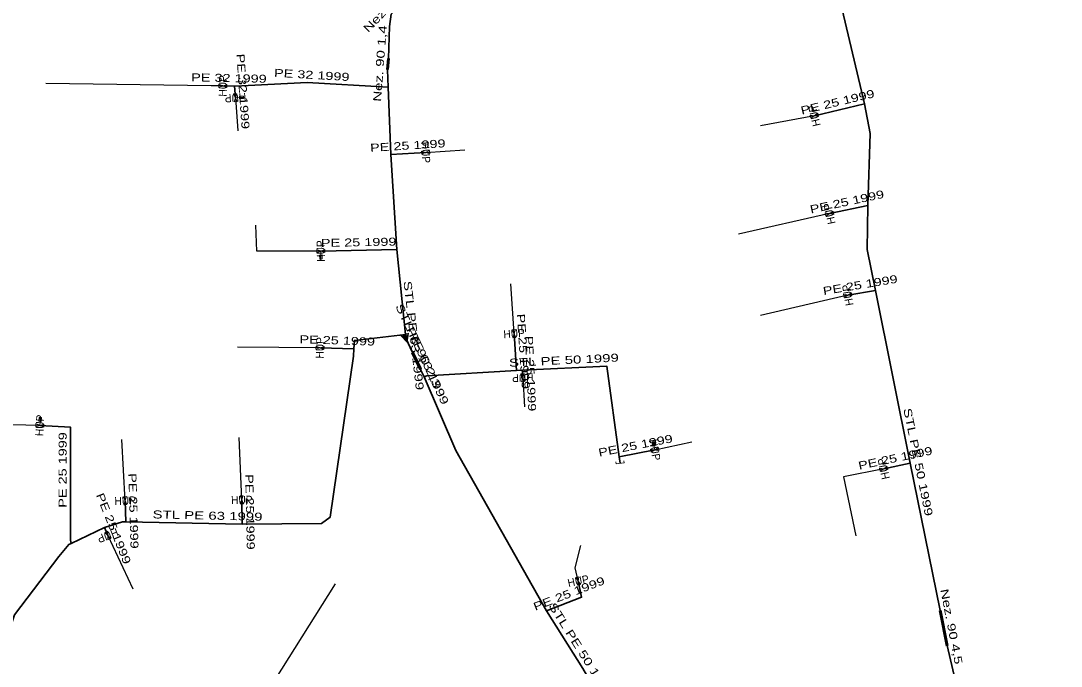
# Model space of a CAD drawing. Extents: x -737484 to -734496, y -1033882 to -1030666.
# Drawn here: x -736219.6 to -736089.6, y -1032200 to -1032119.4 of the extents above; entities that cross this region are included whole.
import ezdxf
from ezdxf.enums import TextEntityAlignment as Align

# ---------------------------------------------------------------- set-up
doc = ezdxf.new("R2010")
doc.units = 0
doc.header["$LTSCALE"] = 0.4
for name, color, linetype, lineweight in [('1', 7, 'Continuous', 13), ('18', 7, 'Continuous', 60), ('22', 7, 'Continuous', 25), ('5', 7, 'Continuous', 35), ('7', 7, 'Continuous', 35)]:
    doc.layers.add(name, color=color, linetype=linetype, lineweight=lineweight)
doc.layers.add('2', color=7, linetype='Continuous')

msp = doc.modelspace()

# ---------------------------------------------------------------- linework, layer by layer
at = {"layer": '1'}
for p, q in [((-736192.759, -1032128.988), (-736192.26, -1032128.953)), ((-736192.18, -1032129.022), (-736191.831, -1032128.998)), ((-736182.163, -1032148.715), (-736182.157, -1032149.065)), ((-736182.099, -1032148.139), (-736182.09, -1032148.638)), ((-736217.199, -1032169.929), (-736217.172, -1032169.429)), ((-736217.094, -1032169.358), (-736217.075, -1032169.009)), ((-736140.406, -1032172.411), (-736140.472, -1032172.067)), ((-736140.37, -1032172.99), (-736140.465, -1032172.499))]:
    msp.add_line(p, q, dxfattribs=at)
for points in [[(-736194.821, -1032127.699), (-736194.814, -1032127.299), (-736193.821, -1032127.716), (-736193.814, -1032127.316)], [(-736192.523, -1032129.473), (-736192.922, -1032129.501), (-736192.593, -1032128.476), (-736192.992, -1032128.504)], [(-736191.761, -1032128.918), (-736191.771, -1032128.768), (-736192.27, -1032128.803), (-736192.26, -1032128.953)], [(-736191.761, -1032128.918), (-736191.75, -1032129.067), (-736192.249, -1032129.102), (-736192.26, -1032128.953)], [(-736191.796, -1032128.957), (-736191.791, -1032129.032), (-736192.215, -1032129.062), (-736192.22, -1032128.987)], [(-736120.861, -1032131.545), (-736120.951, -1032131.155), (-736119.886, -1032131.32), (-736119.976, -1032130.93)], [(-736168.503, -1032135.583), (-736168.475, -1032135.982), (-736169.5, -1032135.653), (-736169.472, -1032136.052)], [(-736118.975, -1032143.766), (-736119.058, -1032143.375), (-736117.997, -1032143.558), (-736118.08, -1032143.167)], [(-736182.595, -1032148.346), (-736182.602, -1032147.946), (-736181.595, -1032148.329), (-736181.602, -1032147.929)], [(-736182.081, -1032149.138), (-736182.231, -1032149.141), (-736182.24, -1032148.641), (-736182.09, -1032148.638)], [(-736182.119, -1032149.101), (-736182.194, -1032149.102), (-736182.201, -1032148.677), (-736182.126, -1032148.676)], [(-736182.081, -1032149.138), (-736181.931, -1032149.136), (-736181.94, -1032148.636), (-736182.09, -1032148.638)], [(-736116.706, -1032153.932), (-736116.776, -1032153.538), (-736115.721, -1032153.759), (-736115.791, -1032153.365)], [(-736158.171, -1032157.975), (-736157.772, -1032157.947), (-736158.101, -1032158.972), (-736157.702, -1032158.944)], [(-736171.117, -1032158.409), (-736172.073, -1032158.702), (-736171.302, -1032159.512)], [(-736171.889, -1032158.75), (-736171.368, -1032159.297), (-736171.242, -1032158.552)], [(-736171.433, -1032159.084), (-736171.368, -1032158.695), (-736171.705, -1032158.798)], [(-736182.695, -1032160.421), (-736182.681, -1032160.021), (-736181.696, -1032160.456), (-736181.682, -1032160.056)], [(-736156.633, -1032164.447), (-736157.032, -1032164.468), (-736156.685, -1032163.449), (-736157.084, -1032163.47)], [(-736217.708, -1032170.103), (-736217.687, -1032169.704), (-736216.71, -1032170.155), (-736216.689, -1032169.756)], [(-736217.146, -1032168.93), (-736217.296, -1032168.922), (-736217.322, -1032169.421), (-736217.172, -1032169.429)], [(-736217.146, -1032168.93), (-736216.996, -1032168.938), (-736217.023, -1032169.437), (-736217.172, -1032169.429)], [(-736217.111, -1032168.97), (-736217.036, -1032168.974), (-736217.059, -1032169.398), (-736217.133, -1032169.394)], [(-736140.56, -1032172.008), (-736140.708, -1032172.036), (-736140.612, -1032172.527), (-736140.465, -1032172.499)], [(-736140.56, -1032172.008), (-736140.413, -1032171.979), (-736140.318, -1032172.47), (-736140.465, -1032172.499)], [(-736140.517, -1032172.038), (-736140.443, -1032172.024), (-736140.362, -1032172.441), (-736140.436, -1032172.455)], [(-736139.915, -1032172.697), (-736139.839, -1032173.089), (-736140.896, -1032172.888), (-736140.82, -1032173.28)], [(-736112.205, -1032175.647), (-736112.288, -1032175.256), (-736111.227, -1032175.439), (-736111.31, -1032175.048)], [(-736206.754, -1032178.846), (-736206.354, -1032178.832), (-736206.719, -1032179.845), (-736206.319, -1032179.831)], [(-736192.175, -1032178.742), (-736191.775, -1032178.735), (-736192.158, -1032179.742), (-736191.758, -1032179.735)], [(-736208.334, -1032184.078), (-736208.705, -1032184.228), (-736208.708, -1032183.151), (-736209.079, -1032183.301)], [(-736150.227, -1032188.921), (-736149.836, -1032188.838), (-736150.019, -1032189.899), (-736149.628, -1032189.816)]]:
    msp.add_lwpolyline(points, close=True, dxfattribs=at)
msp.add_lwpolyline([(-736144.227, -1032174.359), (-736144.201, -1032174.607), (-736145.196, -1032174.712), (-736145.222, -1032174.463)], dxfattribs=at)
at = {"layer": '18'}
for p, q in [((-736173.649, -1032124.079), (-736173.757, -1032125.474)), ((-736170.629, -1032160.809), (-736169.649, -1032162.889)), ((-736104.699, -1032193.049), (-736103.835, -1032197.465))]:
    msp.add_line(p, q, dxfattribs=at)
at = {"layer": '22'}
for p, q in [((-736192.759, -1032128.989), (-736192.456, -1032133.101)), ((-736120.419, -1032131.238), (-736127.164, -1032132.5)), ((-736168.989, -1032135.818), (-736164.104, -1032135.476)), ((-736118.529, -1032143.468), (-736129.897, -1032146.024)), ((-736157.938, -1032158.46), (-736158.357, -1032152.252)), ((-736116.249, -1032153.65), (-736127.165, -1032156.208)), ((-736182.189, -1032160.24), (-736192.489, -1032160.141)), ((-736156.859, -1032163.96), (-736156.624, -1032167.59)), ((-736217.199, -1032169.93), (-736224.514, -1032169.765)), ((-736206.538, -1032179.339), (-736206.972, -1032171.712)), ((-736191.968, -1032179.239), (-736192.293, -1032171.434)), ((-736140.369, -1032172.989), (-736135.718, -1032171.964)), ((-736208.708, -1032183.69), (-736205.582, -1032190.346)), ((-736197.089, -1032216.427), (-736180.237, -1032189.737))]:
    msp.add_line(p, q, dxfattribs=at)
for points in [[(-736194.319, -1032127.509), (-736195.797, -1032127.511), (-736216.466, -1032127.218)], [(-736182.099, -1032148.138), (-736190.084, -1032148.159), (-736190.208, -1032144.91)], [(-736111.759, -1032175.349), (-736116.799, -1032176.355), (-736115.238, -1032183.727)], [(-736149.929, -1032189.369), (-736150.315, -1032187.739), (-736149.597, -1032184.927)]]:
    msp.add_lwpolyline(points, dxfattribs=at)
at = {"layer": '5'}
msp.add_line((-736171.5, -1032158.59), (-736171.449, -1032159.034), dxfattribs=at)
for points in [[(-736127.55, -1032092.63), (-736129.33, -1032094.32), (-736135.68, -1032102.73), (-736135.55, -1032104.58), (-736136.09, -1032105.91), (-736137.95, -1032109.21), (-736147.28, -1032111.54), (-736151.67, -1032112.4), (-736164.82, -1032113.22), (-736168.91, -1032113.53), (-736172.31, -1032116.5), (-736172.49, -1032117.77), (-736173.31, -1032118.56), (-736173.49, -1032120.09), (-736173.65, -1032124.08), (-736173.76, -1032125.5), (-736173.69, -1032127.68), (-736173.33, -1032136.09), (-736172.59, -1032147.96), (-736171.5, -1032158.59)], [(-736127.074, -1032093.129), (-736125.39, -1032094.99), (-736121.45, -1032113.97), (-736118.08, -1032113.18), (-736114.16, -1032129.74), (-736113.45, -1032133.45), (-736113.75, -1032142.44), (-736113.83, -1032147.94), (-736112.8, -1032153.07), (-736108.44, -1032174.65), (-736104.7, -1032193.05), (-736103.84, -1032197.45), (-736102.83, -1032201.73), (-736098.84, -1032214.78), (-736097.14, -1032223.44), (-736096.83, -1032225.37), (-736095.05, -1032238.02), (-736094.44, -1032246.92), (-736092.43, -1032254.14), (-736089.76, -1032259.84), (-736089.579, -1032260.239)], [(-736171.5, -1032158.59), (-736177.9, -1032159.31), (-736177.95, -1032160.38), (-736178, -1032161.29), (-736180.93, -1032181.4), (-736182.02, -1032182.19), (-736191.9, -1032182.29), (-736206.46, -1032181.97), (-736206.89, -1032181.97), (-736209.11, -1032182.68), (-736213.27, -1032184.68), (-736213.59, -1032184.82), (-736214.83, -1032186.32), (-736220.36, -1032193.6), (-736222.02, -1032198.72), (-736221.95, -1032199.37), (-736219.36, -1032205.52), (-736217.3, -1032207.13)], [(-736171.449, -1032159.034), (-736170.63, -1032160.81), (-736169.699, -1032162.788), (-736169.19, -1032163.86)], [(-736169.19, -1032163.86), (-736168.84, -1032163.72), (-736157.62, -1032163.05), (-736156.9, -1032163.03), (-736146.36, -1032162.52), (-736144.79, -1032173.86), (-736144.699, -1032174.66)], [(-736169.19, -1032163.86), (-736165.2, -1032173.06), (-736153.88, -1032193.1), (-736149.35, -1032200.29), (-736145.08, -1032207.68), (-736137.14, -1032220.84), (-736132.88, -1032228.43), (-736131.449, -1032233.05)]]:
    msp.add_lwpolyline(points, dxfattribs=at)
at = {"layer": '7'}
for p, q in [((-736192.86, -1032127.538), (-736194.318, -1032127.508)), ((-736192.86, -1032127.538), (-736192.758, -1032128.989)), ((-736114.16, -1032129.74), (-736120.419, -1032131.238)), ((-736173.33, -1032136.09), (-736168.988, -1032135.818)), ((-736113.75, -1032142.44), (-736118.528, -1032143.467)), ((-736172.59, -1032147.96), (-736182.099, -1032148.138)), ((-736112.8, -1032153.07), (-736116.249, -1032153.649)), ((-736157.62, -1032163.05), (-736157.937, -1032158.46)), ((-736177.95, -1032160.38), (-736182.189, -1032160.239)), ((-736156.9, -1032163.03), (-736156.859, -1032163.959)), ((-736144.79, -1032173.86), (-736140.368, -1032172.989)), ((-736108.44, -1032174.65), (-736111.758, -1032175.348)), ((-736206.46, -1032181.97), (-736206.537, -1032179.339)), ((-736191.9, -1032182.29), (-736191.967, -1032179.239)), ((-736209.11, -1032182.68), (-736208.707, -1032183.69))]:
    msp.add_line(p, q, dxfattribs=at)
for points in [[(-736173.69, -1032127.68), (-736183.78, -1032127.1), (-736192.81, -1032127.54), (-736192.86, -1032127.538)], [(-736213.27, -1032184.68), (-736213.36, -1032184.29), (-736213.35, -1032170.16), (-736217.199, -1032169.93)], [(-736153.88, -1032193.1), (-736149.5, -1032191.41), (-736149.928, -1032189.369)]]:
    msp.add_lwpolyline(points, dxfattribs=at)

# ---------------------------------------------------------------- texts
at = {"layer": '18', "width": 1.4}
for s, rotation, p in [('Nez. 90 2,5', 46.205, (-736172.8495, -1032117.451)), ('Nez. 90 1,4', 85.573, (-736174.2013, -1032124.7376)), ('PE 90 2,3', 295.228, (-736169.6861, -1032161.6354)), ('Nez. 90 4,5', 281.07, (-736103.7763, -1032195.1605))]:
    msp.add_text(s, height=1, rotation=rotation, dxfattribs=at).set_placement(p, align=Align.CENTER)
at = {"layer": '2', "width": 0.95}
for rotation, p in [(89, (-736193.8178, -1032127.5162)), (184, (-736192.7926, -1032128.4896)), (103, (-736119.9315, -1032131.125)), (274, (-736169.4864, -1032135.8526)), (102, (-736118.0388, -1032143.3625)), (91, (-736181.5982, -1032148.1282)), (100, (-736115.7564, -1032153.5613)), (4, (-736157.9014, -1032158.9584)), (88, (-736181.6887, -1032160.2559)), (183, (-736156.8853, -1032163.4595)), (87, (-736216.6995, -1032169.9557)), (281, (-736140.8579, -1032173.0841)), (102, (-736111.2688, -1032175.2435)), (2, (-736206.5189, -1032179.8377)), (1, (-736191.9572, -1032179.7388)), (202, (-736208.8942, -1032183.226)), (12, (-736149.8235, -1032189.8572))]:
    msp.add_text('HUP', height=1, rotation=rotation, dxfattribs=at).set_placement(p, align=Align.CENTER)
at = {"layer": '5', "width": 1.4}
for s, rotation, p in [('STL PE 63 1999', 276.553, (-736170.977, -1032158.7544)), ('STL PE 63 1999', 295.205, (-736169.8754, -1032161.2371)), ('STL PE 50 1999', 2.77, (-736151.6957, -1032162.2772)), ('STL PE 50 1999', 281.489, (-736107.9388, -1032174.6044)), ('STL PE 63 1999', 358.741, (-736196.2525, -1032181.694)), ('STL PE 50 1999', 302.213, (-736150.0182, -1032198.29))]:
    msp.add_text(s, height=1, rotation=rotation, dxfattribs=at).set_placement(p, align=Align.CENTER)
at = {"layer": '7', "width": 1.35}
for s, rotation, p in [('PE 32 1999', 274.021, (-736192.3095, -1032128.2279)), ('PE 32 1999', 356.71, (-736183.2437, -1032126.6294)), ('PE 32 1999', 358.821, (-736193.5783, -1032127.0227)), ('PE 25 1999', 13.46, (-736117.4059, -1032130.002)), ('PE 25 1999', 3.585, (-736171.1893, -1032135.455)), ('PE 25 1999', 12.131, (-736116.2431, -1032142.4645)), ('PE 25 1999', 1.072, (-736177.3529, -1032147.5482)), ('PE 25 1999', 9.53, (-736114.6073, -1032152.8655)), ('PE 25 1999', 273.951, (-736157.2794, -1032160.7206)), ('PE 25 1999', 358.095, (-736180.0526, -1032159.8095)), ('PE 25 1999', 272.527, (-736156.3794, -1032163.472)), ('PE 25 1999', 89.959, (-736213.8536, -1032175.4964)), ('PE 25 1999', 11.143, (-736142.6756, -1032172.9336)), ('PE 25 1999', 11.88, (-736110.2019, -1032174.5091)), ('PE 25 1999', 271.676, (-736205.9986, -1032180.6389)), ('PE 25 1999', 271.258, (-736191.4326, -1032180.753)), ('PE 25 1999', 291.752, (-736208.4435, -1032182.9992)), ('PE 25 1999', 21.099, (-736150.8965, -1032191.4124))]:
    msp.add_text(s, height=1, rotation=rotation, dxfattribs=at).set_placement(p, align=Align.CENTER)

doc.saveas('drawing.dxf')
